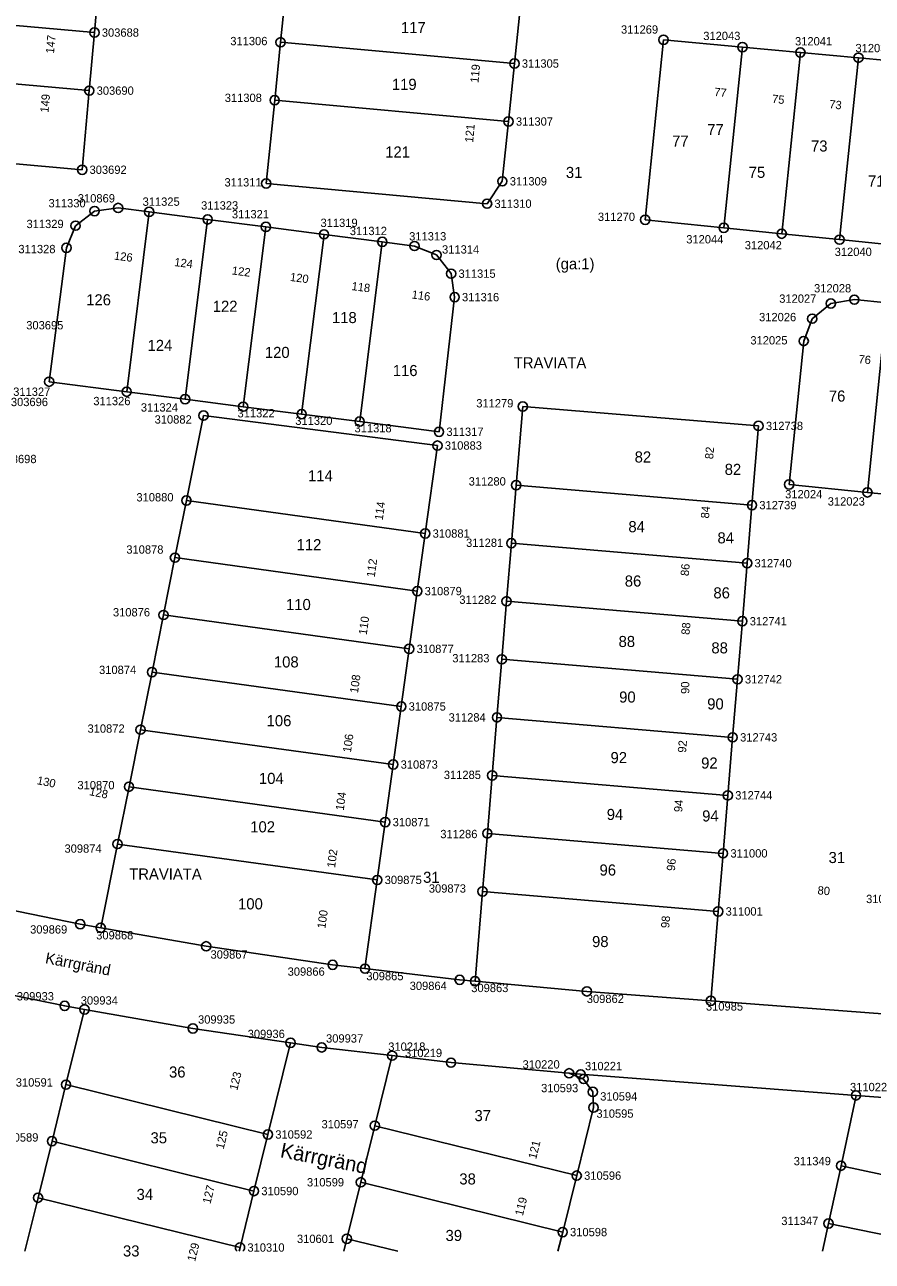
# Model space of a CAD drawing. Extents: x 141995 to 152570, y 6580184 to 6586000.
# Drawn here: x 142153.9 to 142245.6, y 6584998.9 to 6585132.7 of the extents above; entities that cross this region are included whole.
import ezdxf

# ---------------------------------------------------------------- set-up
doc = ezdxf.new("R2010")
doc.units = 0
for name, color, linetype in [('Level 10', 7, 'Continuous'), ('Level 40', 7, 'Continuous'), ('Level 43', 7, 'Continuous'), ('Level 5', 7, 'Continuous'), ('Level 51', 7, 'Continuous'), ('Level 53', 7, 'Continuous'), ('Level 54', 7, 'Continuous'), ('Level 58', 7, 'Continuous'), ('Level 59', 7, 'Continuous'), ('Level 6', 7, 'Continuous'), ('Level 7', 7, 'Continuous')]:
    doc.layers.add(name, color=color, linetype=linetype)

msp = doc.modelspace()

# ---------------------------------------------------------------- linework, layer by layer
at = {"layer": 'Level 10'}
for centre in [(142161.49, 6585131.84), (142181.63, 6585130.79), (142223.06, 6585131.06), (142231.6, 6585130.27), (142237.87, 6585129.69), (142244.15, 6585129.12), (142206.93, 6585128.49), (142160.93, 6585125.56), (142180.99, 6585124.52), (142206.29, 6585122.22), (142160.16, 6585117), (142180.07, 6585115.51), (142205.62, 6585115.75), (142164.06, 6585112.87), (142203.97, 6585113.33), (142161.5, 6585112.53), (142167.41, 6585112.44), (142173.74, 6585111.63), (142221.08, 6585111.59), (142159.45, 6585110.95), (142180.04, 6585110.82), (142229.58, 6585110.72), (142186.33, 6585110.01), (142192.63, 6585109.2), (142235.85, 6585110.08), (142242.11, 6585109.44), (142158.46, 6585108.56), (142196.12, 6585108.75), (142198.5, 6585107.78), (142200.08, 6585105.76), (142200.46, 6585103.22), (142241.16, 6585102.53), (142243.71, 6585102.95), (142239.15, 6585100.89), (142238.23, 6585098.47), (142156.59, 6585094.07), (142164.98, 6585092.99), (142171.3, 6585092.18), (142173.29, 6585090.41), (142177.59, 6585091.37), (142183.91, 6585090.56), (142207.83, 6585091.39), (142190.19, 6585089.76), (142233.34, 6585089.29), (142198.77, 6585088.65), (142198.6, 6585087.16), (142207.12, 6585082.88), (142236.65, 6585082.96), (142245.12, 6585082.1), (142171.44, 6585081.22), (142232.63, 6585080.72), (142197.28, 6585077.65), (142206.6, 6585076.6), (142170.2, 6585075.04), (142232.11, 6585074.44), (142196.42, 6585071.42), (142206.08, 6585070.32), (142168.96, 6585068.84), (142231.59, 6585068.16), (142195.55, 6585065.17), (142205.56, 6585064.04), (142167.72, 6585062.66), (142231.07, 6585061.88), (142194.69, 6585058.94), (142205.04, 6585057.76), (142166.47, 6585056.43), (142230.54, 6585055.6), (142193.82, 6585052.66), (142204.52, 6585051.48), (142165.23, 6585050.26), (142230.02, 6585049.32), (142192.95, 6585046.43), (142204, 6585045.21), (142163.99, 6585044.06), (142229.5, 6585043.05), (142192.09, 6585040.17), (142203.48, 6585038.93), (142228.98, 6585036.77), (142159.95, 6585035.39), (142162.17, 6585035), (142173.58, 6585033), (142187.26, 6585030.99), (142190.76, 6585030.58), (142201, 6585029.37), (142202.67, 6585029.22), (142214.77, 6585028.12), (142158.27, 6585026.55), (142160.42, 6585026.17), (142228.18, 6585027.1), (142172.14, 6585024.11), (142182.71, 6585022.56), (142186.08, 6585022.06), (142193.7, 6585021.17), (142200.07, 6585020.41), (142212.85, 6585019.26), (142158.41, 6585018.03), (142214.09, 6585019.15), (142214.42, 6585018.64), (142215.41, 6585017.25), (142243.89, 6585016.87), (142215.48, 6585015.55), (142180.26, 6585012.64), (142191.82, 6585013.59), (142156.9, 6585011.92), (142242.27, 6585009.26), (142190.31, 6585007.47), (142213.67, 6585008.19), (142178.75, 6585006.52), (142155.39, 6585005.8), (142212.15, 6585002.08), (142240.92, 6585003.01), (142188.8, 6585001.36)]:
    msp.add_circle(centre, 0.5, dxfattribs=at)
msp.add_arc((142177.24, 6585000.41), 0.5, 305.7486, 234.2514, dxfattribs=at)
at = {"layer": 'Level 5'}
for points in [[(142159.95, 6585035.39), (142146.4, 6585038.16)], [(142162.17, 6585035), (142159.95, 6585035.39)], [(142173.58, 6585033), (142162.17, 6585035)], [(142187.26, 6585030.99), (142173.58, 6585033)], [(142190.76, 6585030.58), (142187.26, 6585030.99)], [(142201, 6585029.37), (142190.76, 6585030.58)], [(142158.27, 6585026.55), (142144.48, 6585029.36)], [(142202.67, 6585029.22), (142201, 6585029.37)], [(142214.77, 6585028.12), (142202.67, 6585029.22)], [(142214.77, 6585028.12), (142228.18, 6585027.1)], [(142160.42, 6585026.17), (142158.27, 6585026.55)], [(142249.62, 6585025.47), (142228.18, 6585027.1)], [(142160.42, 6585026.17), (142172.14, 6585024.11)], [(142172.14, 6585024.11), (142182.71, 6585022.56)], [(142186.08, 6585022.06), (142182.71, 6585022.56)], [(142193.7, 6585021.17), (142186.08, 6585022.06)], [(142193.7, 6585021.17), (142200.07, 6585020.41)], [(142200.07, 6585020.41), (142212.85, 6585019.26)], [(142214.09, 6585019.15), (142212.85, 6585019.26)], [(142214.09, 6585019.15), (142243.89, 6585016.87)], [(142243.89, 6585016.87), (142266.53, 6585015.16)]]:
    msp.add_lwpolyline(points, dxfattribs=at)
at = {"layer": 'Level 6'}
for points in [[(142084, 6585050.59), (142099.8, 6585048.31), (142112.19, 6585045.62), (142114.63, 6585045.08), (142141.12, 6585039.31), (142146.4, 6585038.16), (142159.95, 6585035.39), (142162.17, 6585035), (142173.58, 6585033), (142187.26, 6585030.99), (142190.76, 6585030.58), (142201, 6585029.37), (142202.67, 6585029.22)], [(142266.53, 6585015.16), (142243.89, 6585016.87), (142214.09, 6585019.15), (142212.85, 6585019.26), (142200.07, 6585020.41), (142193.7, 6585021.17), (142186.08, 6585022.06), (142182.71, 6585022.56), (142172.14, 6585024.11), (142160.42, 6585026.17), (142158.27, 6585026.55), (142144.48, 6585029.36), (142130.52, 6585032.42), (142110.69, 6585036.76), (142107.54, 6585037.45), (142100.73, 6585034.01), (142098.08, 6585030.38), (142078.78, 6585033.15), (142075.89, 6585024.79), (142073.13, 6585016.81), (142071.07, 6585010.85), (142069.02, 6585004.9), (142067.33, 6585000)], [(142202.67, 6585029.22), (142214.77, 6585028.12), (142228.18, 6585027.1), (142249.62, 6585025.47)]]:
    msp.add_lwpolyline(points, dxfattribs=at)
at = {"layer": 'Level 7'}
for points in [[(142161.49, 6585131.84), (142162.05, 6585138.11)], [(142182.27, 6585137.06), (142181.63, 6585130.79)], [(142206.93, 6585128.49), (142207.57, 6585134.76)], [(142161.49, 6585131.84), (142136.35, 6585134.09)], [(142160.93, 6585125.56), (142161.49, 6585131.84)], [(142181.63, 6585130.79), (142180.99, 6585124.52)], [(142206.93, 6585128.49), (142181.63, 6585130.79)], [(142221.08, 6585111.59), (142223.06, 6585131.06)], [(142223.06, 6585131.06), (142231.6, 6585130.27)], [(142231.6, 6585130.27), (142229.58, 6585110.72)], [(142231.6, 6585130.27), (142237.87, 6585129.69)], [(142235.85, 6585110.08), (142237.87, 6585129.69)], [(142237.87, 6585129.69), (142244.15, 6585129.12)], [(142206.29, 6585122.22), (142206.93, 6585128.49)], [(142242.11, 6585109.44), (142244.15, 6585129.12)], [(142244.15, 6585129.12), (142250.42, 6585128.53)], [(142160.93, 6585125.56), (142135.79, 6585127.82)], [(142160.16, 6585117), (142160.93, 6585125.56)], [(142180.99, 6585124.52), (142180.07, 6585115.51)], [(142206.29, 6585122.22), (142180.99, 6585124.52)], [(142205.62, 6585115.75), (142206.29, 6585122.22)], [(142135.02, 6585119.26), (142160.16, 6585117)], [(142180.07, 6585115.51), (142203.97, 6585113.33)], [(142203.97, 6585113.33), (142205.62, 6585115.75)], [(142159.45, 6585110.95), (142161.5, 6585112.53)], [(142161.5, 6585112.53), (142164.06, 6585112.87)], [(142164.06, 6585112.87), (142167.41, 6585112.44)], [(142164.98, 6585092.99), (142167.41, 6585112.44)], [(142167.41, 6585112.44), (142173.74, 6585111.63)], [(142158.46, 6585108.56), (142159.45, 6585110.95)], [(142171.3, 6585092.18), (142173.74, 6585111.63)], [(142173.74, 6585111.63), (142180.04, 6585110.82)], [(142177.59, 6585091.37), (142180.04, 6585110.82)], [(142180.04, 6585110.82), (142186.33, 6585110.01)], [(142221.08, 6585111.59), (142229.58, 6585110.72)], [(142235.85, 6585110.08), (142229.58, 6585110.72)], [(142183.91, 6585090.56), (142186.33, 6585110.01)], [(142186.33, 6585110.01), (142192.63, 6585109.2)], [(142242.11, 6585109.44), (142235.85, 6585110.08)], [(142248.37, 6585108.81), (142242.11, 6585109.44)], [(142156.59, 6585094.07), (142158.46, 6585108.56)], [(142190.19, 6585089.76), (142192.63, 6585109.2)], [(142192.63, 6585109.2), (142196.12, 6585108.75)], [(142196.12, 6585108.75), (142198.5, 6585107.78)], [(142198.5, 6585107.78), (142200.08, 6585105.76)], [(142200.08, 6585105.76), (142200.46, 6585103.22)], [(142200.46, 6585103.22), (142198.77, 6585088.65)], [(142241.16, 6585102.53), (142243.71, 6585102.95)], [(142243.71, 6585102.95), (142247.24, 6585102.59)], [(142239.15, 6585100.89), (142241.16, 6585102.53)], [(142245.12, 6585082.1), (142247.24, 6585102.59)], [(142238.23, 6585098.47), (142239.15, 6585100.89)], [(142236.65, 6585082.96), (142238.23, 6585098.47)], [(142164.98, 6585092.99), (142156.59, 6585094.07)], [(142171.3, 6585092.18), (142164.98, 6585092.99)], [(142177.59, 6585091.37), (142171.3, 6585092.18)], [(142183.91, 6585090.56), (142177.59, 6585091.37)], [(142207.83, 6585091.39), (142207.12, 6585082.88)], [(142207.83, 6585091.39), (142233.34, 6585089.29)], [(142173.29, 6585090.41), (142171.44, 6585081.22)], [(142198.6, 6585087.16), (142173.29, 6585090.41)], [(142190.19, 6585089.76), (142183.91, 6585090.56)], [(142198.77, 6585088.65), (142190.19, 6585089.76)], [(142232.63, 6585080.72), (142233.34, 6585089.29)], [(142197.28, 6585077.65), (142198.6, 6585087.16)], [(142207.12, 6585082.88), (142206.6, 6585076.6)], [(142207.12, 6585082.88), (142232.63, 6585080.72)], [(142245.12, 6585082.1), (142236.65, 6585082.96)], [(142251.39, 6585081.46), (142245.12, 6585082.1)], [(142171.44, 6585081.22), (142170.2, 6585075.04)], [(142171.44, 6585081.22), (142197.28, 6585077.65)], [(142232.11, 6585074.44), (142232.63, 6585080.72)], [(142196.42, 6585071.42), (142197.28, 6585077.65)], [(142206.6, 6585076.6), (142206.08, 6585070.32)], [(142206.6, 6585076.6), (142232.11, 6585074.44)], [(142170.2, 6585075.04), (142168.96, 6585068.84)], [(142170.2, 6585075.04), (142196.42, 6585071.42)], [(142231.59, 6585068.16), (142232.11, 6585074.44)], [(142195.55, 6585065.17), (142196.42, 6585071.42)], [(142206.08, 6585070.32), (142205.56, 6585064.04)], [(142206.08, 6585070.32), (142231.59, 6585068.16)], [(142168.96, 6585068.84), (142167.72, 6585062.66)], [(142168.96, 6585068.84), (142195.55, 6585065.17)], [(142231.07, 6585061.88), (142231.59, 6585068.16)], [(142194.69, 6585058.94), (142195.55, 6585065.17)], [(142205.56, 6585064.04), (142205.04, 6585057.76)], [(142205.56, 6585064.04), (142231.07, 6585061.88)], [(142167.72, 6585062.66), (142166.47, 6585056.43)], [(142167.72, 6585062.66), (142194.69, 6585058.94)], [(142230.54, 6585055.6), (142231.07, 6585061.88)], [(142193.82, 6585052.66), (142194.69, 6585058.94)], [(142205.04, 6585057.76), (142204.52, 6585051.48)], [(142205.04, 6585057.76), (142230.54, 6585055.6)], [(142166.47, 6585056.43), (142165.23, 6585050.26)], [(142166.47, 6585056.43), (142193.82, 6585052.66)], [(142230.02, 6585049.32), (142230.54, 6585055.6)], [(142192.95, 6585046.43), (142193.82, 6585052.66)], [(142204.52, 6585051.48), (142204, 6585045.21)], [(142204.52, 6585051.48), (142230.02, 6585049.32)], [(142165.23, 6585050.26), (142163.99, 6585044.06)], [(142165.23, 6585050.26), (142192.95, 6585046.43)], [(142230.02, 6585049.32), (142229.5, 6585043.05)], [(142192.95, 6585046.43), (142192.09, 6585040.17)], [(142204, 6585045.21), (142203.48, 6585038.93)], [(142204, 6585045.21), (142229.5, 6585043.05)], [(142163.99, 6585044.06), (142162.17, 6585035)], [(142163.99, 6585044.06), (142192.09, 6585040.17)], [(142228.98, 6585036.77), (142229.5, 6585043.05)], [(142190.76, 6585030.58), (142192.09, 6585040.17)], [(142203.48, 6585038.93), (142202.67, 6585029.22)], [(142203.48, 6585038.93), (142228.98, 6585036.77)], [(142228.18, 6585027.1), (142228.98, 6585036.77)], [(142158.41, 6585018.03), (142160.42, 6585026.17)], [(142182.71, 6585022.56), (142180.26, 6585012.64)], [(142191.82, 6585013.59), (142193.7, 6585021.17)], [(142212.85, 6585019.26), (142214.42, 6585018.64)], [(142214.42, 6585018.64), (142215.41, 6585017.25)], [(142156.9, 6585011.92), (142158.41, 6585018.03)], [(142158.41, 6585018.03), (142180.26, 6585012.64)], [(142215.41, 6585017.25), (142215.48, 6585015.55)], [(142242.27, 6585009.26), (142243.89, 6585016.87)], [(142215.48, 6585015.55), (142213.67, 6585008.19)], [(142190.31, 6585007.47), (142191.82, 6585013.59)], [(142213.67, 6585008.19), (142191.82, 6585013.59)], [(142155.39, 6585005.8), (142156.9, 6585011.92)], [(142156.9, 6585011.92), (142178.75, 6585006.52)], [(142180.26, 6585012.64), (142178.75, 6585006.52)], [(142240.92, 6585003.01), (142242.27, 6585009.26)], [(142242.27, 6585009.26), (142264.27, 6585004.56)], [(142213.67, 6585008.19), (142212.15, 6585002.08)], [(142178.75, 6585006.52), (142177.24, 6585000.41)], [(142188.8, 6585001.36), (142190.31, 6585007.47)], [(142212.15, 6585002.08), (142190.31, 6585007.47)], [(142153.96, 6585000), (142155.39, 6585005.8)], [(142155.39, 6585005.8), (142177.24, 6585000.41)], [(142240.28, 6585000), (142240.92, 6585003.01)], [(142240.92, 6585003.01), (142255.55, 6585000)], [(142188.47, 6585000), (142188.8, 6585001.36)], [(142194.3, 6585000), (142188.8, 6585001.36)], [(142212.15, 6585002.08), (142211.64, 6585000)], [(142177.24, 6585000.41), (142177.14, 6585000)]]:
    msp.add_lwpolyline(points, dxfattribs=at)

# ---------------------------------------------------------------- texts
at = {"layer": 'Level 40'}
msp.add_text('Kärrgränd', height=1.2, rotation=348.9089, dxfattribs=at).set_placement((142156.1, 6585031.18))
at = {"layer": 'Level 43'}
msp.add_text('Kärrgränd', height=1.6, rotation=348.9089, dxfattribs=at).set_placement((142181.51, 6585010.2))
at = {"layer": 'Level 51'}
for s, rotation, p in [('117', 0.0526, (142194.65, 6585131.78)), ('119', 0.0526, (142193.67, 6585125.64)), ('77', 0.0522, (142223.99, 6585119.5)), ('73', 0.0522, (142239.02, 6585118.97)), ('121', 0.0526, (142192.95, 6585118.32)), ('75', 0.0522, (142232.28, 6585116.12)), ('71', 0.0522, (142245.19, 6585115.18)), ('(ga:1)', 0.0522, (142211.4, 6585106.23)), ('126', 0.0526, (142160.6, 6585102.33)), ('122', 0.0526, (142174.29, 6585101.63)), ('118', 0.0522, (142187.19, 6585100.41)), ('124', 0.0526, (142167.24, 6585097.4)), ('120', 0.0522, (142179.93, 6585096.64)), ('116', 0.0522, (142193.77, 6585094.68)), ('76', 0.0522, (142240.95, 6585091.92)), ('82', 0.0522, (142219.94, 6585085.33)), ('114', 0.0522, (142184.6, 6585083.3)), ('84', 0.0522, (142219.26, 6585077.79)), ('112', 0.0522, (142183.36, 6585075.84)), ('86', 0.0522, (142218.87, 6585071.91)), ('110', 0.0522, (142182.22, 6585069.37)), ('88', 0.0522, (142218.2, 6585065.37)), ('108', 0.0522, (142180.91, 6585063.16)), ('90', 0.0522, (142218.26, 6585059.36)), ('106', 0.0522, (142180.12, 6585056.8)), ('92', 0.0522, (142217.33, 6585052.81)), ('104', 0.0522, (142179.29, 6585050.56)), ('94', 0.0522, (142216.92, 6585046.66)), ('102', 0.0522, (142178.35, 6585045.32)), ('96', 0.0522, (142216.14, 6585040.65)), ('100', 0.0522, (142177.03, 6585036.99)), ('98', 0.0522, (142215.33, 6585032.91)), ('36', 0.0522, (142169.56, 6585018.8)), ('37', 0.0522, (142202.61, 6585014.08)), ('35', 0.0522, (142167.56, 6585011.68)), ('38', 0.0522, (142200.97, 6585007.23)), ('34', 0.0522, (142166.05, 6585005.56)), ('39', 0.0522, (142199.48, 6585001.12)), ('33', 0.0522, (142164.58, 6584999.44))]:
    msp.add_text(s, height=1.2, rotation=rotation, dxfattribs=at).set_placement(p)
at = {"layer": 'Level 53'}
for s, rotation, p in [('303688', 0.0526, (142162.29, 6585131.39)), ('311269', 0.0526, (142218.46, 6585131.72)), ('311306', 0.0526, (142176.19, 6585130.47)), ('312043', 0.0526, (142227.36, 6585131.03)), ('312041', 0.0522, (142237.29, 6585130.45)), ('312039', 0.0522, (142243.83, 6585129.71)), ('311305', 0.0526, (142207.73, 6585128.04)), ('303690', 0.0526, (142161.73, 6585125.11)), ('311308', 0.0526, (142175.59, 6585124.33)), ('311307', 0.0526, (142207.09, 6585121.77)), ('303692', 0.0526, (142160.96, 6585116.55)), ('311311', 0.0526, (142175.56, 6585115.19)), ('311309', 0.0526, (142206.43, 6585115.3)), ('311330', 0.0526, (142156.52, 6585112.93)), ('310869', 0.0526, (142159.69, 6585113.46)), ('311325', 0.0526, (142166.7, 6585113.1)), ('311323', 0.0526, (142173.03, 6585112.69)), ('311310', 0.0522, (142204.77, 6585112.88)), ('311321', 0.0526, (142176.36, 6585111.74)), ('311270', 0.0522, (142215.96, 6585111.46)), ('311329', 0.0526, (142154.14, 6585110.69)), ('311319', 0.0526, (142185.95, 6585110.81)), ('311312', 0.0526, (142189.12, 6585109.93)), ('311313', 0.0526, (142195.54, 6585109.35)), ('312044', 0.0522, (142225.52, 6585109.03)), ('311328', 0.0526, (142153.26, 6585107.97)), ('311314', 0.0522, (142199.1, 6585107.93)), ('312042', 0.0522, (142231.85, 6585108.39)), ('312040', 0.0522, (142241.58, 6585107.67)), ('311315', 0.0522, (142200.88, 6585105.31)), ('312028', 0.0522, (142239.35, 6585103.73)), ('311316', 0.0522, (142201.26, 6585102.77)), ('312027', 0.0522, (142235.58, 6585102.61)), ('312026', 0.0522, (142233.4, 6585100.61)), ('303695', 0.0526, (142154.11, 6585099.73)), ('312025', 0.0522, (142232.46, 6585098.1)), ('311327', 0.0526, (142152.7, 6585092.54)), ('303696', 0.0526, (142152.45, 6585091.43)), ('311326', 0.0526, (142161.37, 6585091.53)), ('311279', 0.0522, (142202.8, 6585091.29)), ('311324', 0.0522, (142166.51, 6585090.84)), ('311322', 0.0522, (142176.97, 6585090.21)), ('310882', 0.0522, (142168, 6585089.54)), ('311320', 0.0522, (142183.22, 6585089.4)), ('311318', 0.0522, (142189.63, 6585088.59)), ('312738', 0.0522, (142234.14, 6585088.84)), ('311317', 0.0522, (142199.57, 6585088.21)), ('310883', 0.0522, (142199.4, 6585086.72)), ('303698', 0.0526, (142151.21, 6585085.26)), ('311280', 0.0522, (142201.98, 6585082.84)), ('310880', 0.0522, (142166.03, 6585081.12)), ('312024', 0.0522, (142236.22, 6585081.45)), ('312023', 0.0522, (142240.83, 6585080.67)), ('312739', 0.0522, (142233.43, 6585080.27)), ('310881', 0.0522, (142198.08, 6585077.2)), ('310878', 0.0522, (142164.94, 6585075.47)), ('311281', 0.0522, (142201.7, 6585076.2)), ('312740', 0.0522, (142232.91, 6585073.99)), ('310879', 0.0522, (142197.22, 6585070.97)), ('311282', 0.0522, (142200.97, 6585070.04)), ('310876', 0.0522, (142163.49, 6585068.68)), ('312741', 0.0522, (142232.39, 6585067.71)), ('310877', 0.0522, (142196.35, 6585064.72)), ('311283', 0.0522, (142200.21, 6585063.71)), ('310874', 0.0522, (142161.99, 6585062.45)), ('312742', 0.0522, (142231.87, 6585061.43)), ('310875', 0.0522, (142195.49, 6585058.49)), ('311284', 0.0522, (142199.81, 6585057.31)), ('310872', 0.0522, (142160.74, 6585056.1)), ('312743', 0.0522, (142231.35, 6585055.15)), ('310873', 0.0522, (142194.62, 6585052.21)), ('311285', 0.0522, (142199.29, 6585051.09)), ('310870', 0.0522, (142159.65, 6585049.98)), ('312744', 0.0522, (142230.82, 6585048.88)), ('310871', 0.0522, (142193.76, 6585045.98)), ('311286', 0.0522, (142198.91, 6585044.69)), ('309874', 0.0522, (142158.25, 6585043.12)), ('311000', 0.0522, (142230.3, 6585042.6)), ('309875', 0.0522, (142192.89, 6585039.73)), ('309873', 0.0522, (142197.67, 6585038.8)), ('310997', 0.0522, (142244.98, 6585037.67)), ('311001', 0.0522, (142229.78, 6585036.32)), ('309869', 0.0522, (142154.53, 6585034.37)), ('309868', 0.0522, (142161.68, 6585033.74)), ('309867', 0.0522, (142174.05, 6585031.66)), ('309866', 0.0522, (142182.39, 6585029.81)), ('309865', 0.0522, (142190.91, 6585029.32)), ('309864', 0.0522, (142195.6, 6585028.27)), ('309933', 0.0522, (142153.09, 6585027.14)), ('309863', 0.0522, (142202.26, 6585028.04)), ('309862', 0.0522, (142214.76, 6585026.86)), ('309934', 0.0522, (142160.01, 6585026.69)), ('310985', 0.0522, (142227.65, 6585026.04)), ('309935', 0.0522, (142172.7, 6585024.63)), ('309936', 0.0522, (142178.07, 6585023.07)), ('309937', 0.0522, (142186.55, 6585022.58)), ('310218', 0.0522, (142193.28, 6585021.69)), ('310219', 0.0522, (142195.09, 6585021.01)), ('310220', 0.0522, (142207.81, 6585019.77)), ('310221', 0.0522, (142214.57, 6585019.59)), ('310591', 0.0522, (142152.98, 6585017.82)), ('310593', 0.0522, (142209.82, 6585017.21)), ('310594', 0.0522, (142216.21, 6585016.31)), ('311022', 0.0522, (142243.24, 6585017.32)), ('310595', 0.0522, (142215.8, 6585014.45)), ('310592', 0.0522, (142181.06, 6585012.19)), ('310597', 0.0522, (142186.06, 6585013.3)), ('310589', 0.0522, (142151.41, 6585011.87)), ('311349', 0.0522, (142237.15, 6585009.31)), ('310599', 0.0522, (142184.48, 6585007.02)), ('310596', 0.0522, (142214.47, 6585007.74)), ('310590', 0.0522, (142179.55, 6585006.07)), ('311347', 0.0522, (142235.8, 6585002.84)), ('310598', 0.0522, (142212.95, 6585001.63)), ('310601', 0.0522, (142183.4, 6585000.9)), ('310310', 0.0522, (142178.04, 6584999.96))]:
    msp.add_text(s, height=0.9, rotation=rotation, dxfattribs=at).set_placement(p)
at = {"layer": 'Level 54'}
for s, rotation, p in [('147', 84.7935, (142157.11, 6585129.54)), ('119', 84.8315, (142203.04, 6585126.37)), ('77', 354.1531, (142228.51, 6585124.99)), ('149', 84.7955, (142156.51, 6585123.15)), ('75', 354.1521, (142234.77, 6585124.24)), ('73', 354.1531, (142240.96, 6585123.66)), ('121', 84.8315, (142202.46, 6585119.91)), ('126', 352.6438, (142163.57, 6585107.29)), ('124', 352.6508, (142170.09, 6585106.59)), ('122', 352.6498, (142176.32, 6585105.68)), ('120', 352.6498, (142182.61, 6585104.98)), ('118', 352.649, (142189.27, 6585103.99)), ('116', 352.644, (142195.78, 6585103.08)), ('76', 354.2101, (142244.12, 6585096.09)), ('82', 85.1288, (142228.43, 6585085.66)), ('114', 82.0789, (142192.68, 6585079.04)), ('84', 85.1328, (142227.98, 6585079.25)), ('112', 82.0779, (142191.81, 6585072.87)), ('86', 85.1308, (142225.79, 6585073.02)), ('110', 82.0769, (142190.95, 6585066.64)), ('88', 85.1298, (142225.87, 6585066.66)), ('108', 82.0779, (142190, 6585060.34)), ('90', 90.0497, (142225.85, 6585060.3)), ('106', 82.0708, (142189.24, 6585053.92)), ('92', 85.1328, (142225.49, 6585053.91)), ('130', 348.5739, (142155.22, 6585050.54)), ('128', 348.5739, (142160.88, 6585049.36)), ('104', 82.0789, (142188.46, 6585047.64)), ('94', 85.1368, (142225.08, 6585047.47)), ('102', 82.0759, (142187.52, 6585041.45)), ('96', 85.1288, (142224.29, 6585041.12)), ('80', 355.3371, (142239.7, 6585038.62)), ('100', 82.0779, (142186.47, 6585034.87)), ('98', 85.1308, (142223.67, 6585034.93)), ('123', 76.156, (142176.94, 6585017.35)), ('125', 76.153, (142175.46, 6585010.99)), ('121', 76.131, (142209.28, 6585009.92)), ('127', 76.152, (142174.04, 6585005.08)), ('119', 76.137, (142207.84, 6585003.78)), ('129', 76.153, (142172.38, 6584998.84))]:
    msp.add_text(s, height=0.9, rotation=rotation, dxfattribs=at).set_placement(p)
at = {"layer": 'Level 58'}
for rotation, p in [(0.0522, (142206.86, 6585095.52)), (359.9242, (142165.25, 6585040.22))]:
    msp.add_text('TRAVIATA', height=1.2, rotation=rotation, dxfattribs=at).set_placement(p)
at = {"layer": 'Level 59'}
for s, p in [('77', (142227.79, 6585120.75)), ('31', (142212.5, 6585116.11)), ('82', (142229.68, 6585083.99)), ('84', (142228.9, 6585076.58)), ('86', (142228.46, 6585070.63)), ('88', (142228.24, 6585064.68)), ('90', (142227.79, 6585058.62)), ('92', (142227.13, 6585052.22)), ('94', (142227.24, 6585046.5)), ('31', (142240.92, 6585042)), ('31', (142197.05, 6585039.86))]:
    msp.add_text(s, height=1.2, rotation=0.0522, dxfattribs=at).set_placement(p)

doc.saveas('drawing.dxf')
